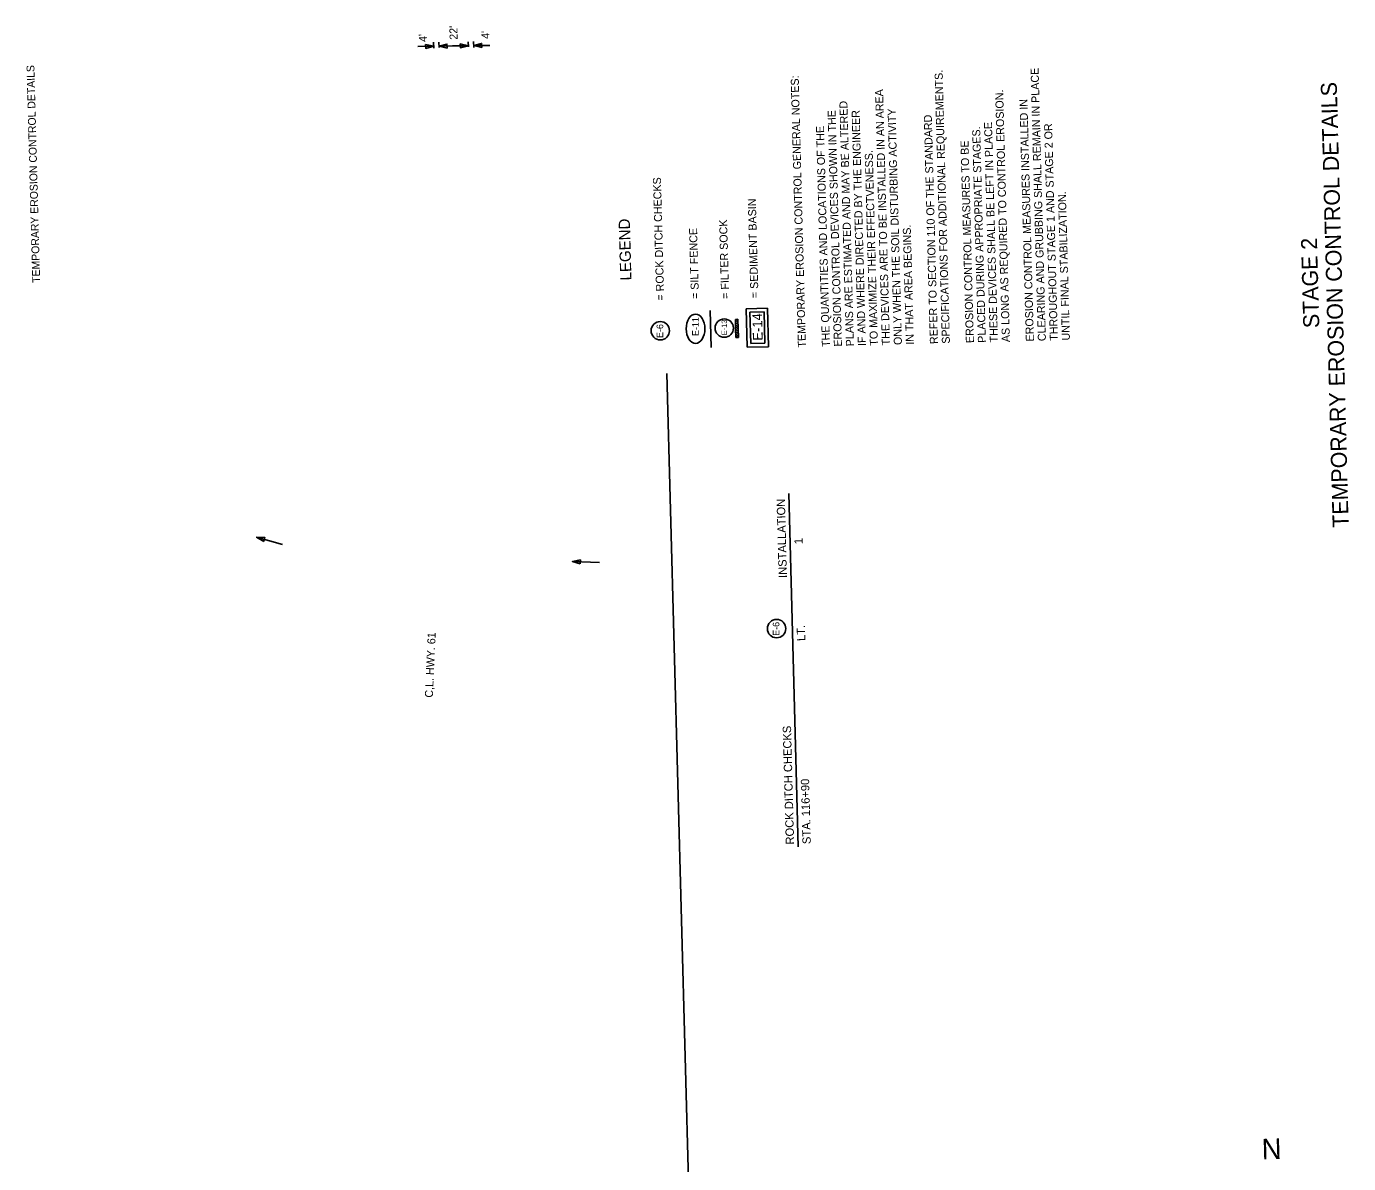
# Model space of a CAD drawing. Extents: x 1930579 to 1931599, y 596452 to 598574.
# Drawn here: x 1930608 to 1931599, y 597722 to 598574 of the extents above; entities that cross this region are included whole.
import ezdxf

# ---------------------------------------------------------------- set-up
doc = ezdxf.new("R2010")
doc.units = 0
for name, color, linetype in [('Default', 7, 'Continuous'), ('R_Annotation', 7, 'Continuous'), ('R_Border', 7, 'Continuous'), ('R_Erosion', 7, 'Continuous')]:
    doc.layers.add(name, color=color, linetype=linetype)

msp = doc.modelspace()

# ---------------------------------------------------------------- linework, layer by layer
at = {"layer": 'Default'}
msp.add_line((1931186.46, 597959.13), (1931179.35, 598224.08), dxfattribs=at)
at = {"layer": 'R_Annotation'}
for p, q in [((1930913.15, 598559.55), (1930901.15, 598559.36)), ((1930913.17, 598558.16), (1930913.1, 598562.55)), ((1930917.17, 598558.69), (1930917.1, 598562.61)), ((1930917.15, 598559.61), (1930939.15, 598559.96)), ((1930929.15, 598559.8), (1930917.15, 598559.61)), ((1930939.15, 598559.96), (1930927.15, 598559.77)), ((1930939.16, 598559.05), (1930939.1, 598562.96)), ((1930943.17, 598558.62), (1930943.1, 598563.03)), ((1930955.15, 598560.22), (1930943.15, 598560.03)), ((1930780.38, 598191.25), (1930799.88, 598185.77)), ((1931017.13, 598173), (1931037.38, 598172.23))]:
    msp.add_line(p, q, dxfattribs=at)
for points in [[(1930907.13, 598560.95), (1930913.15, 598559.55), (1930907.18, 598557.95)], [(1930923.17, 598558.21), (1930917.15, 598559.61), (1930923.13, 598561.21)], [(1930923.17, 598558.21), (1930917.15, 598559.61), (1930923.13, 598561.21)], [(1930933.13, 598561.37), (1930939.15, 598559.96), (1930933.17, 598558.37)], [(1930933.13, 598561.37), (1930939.15, 598559.96), (1930933.17, 598558.37)], [(1930949.17, 598558.62), (1930943.15, 598560.03), (1930949.12, 598561.62)], [(1930785.75, 598188.18), (1930780.38, 598191.25), (1930786.56, 598191.07)], [(1931023.07, 598171.27), (1931017.13, 598173), (1931023.19, 598174.27)]]:
    msp.add_lwpolyline(points, close=True, dxfattribs=at)
at = {"layer": 'R_Border'}
msp.add_line((1931105.18, 597672.96), (1931087.97, 598314.03), dxfattribs=at)
at = {"layer": 'R_Erosion'}
for p, q in [((1931147.54, 598362.6), (1931163.53, 598363.03)), ((1931148.31, 598333.76), (1931147.54, 598362.6)), ((1931150.32, 598359.97), (1931160.9, 598360.26)), ((1931150.94, 598336.54), (1931150.32, 598359.97)), ((1931161.53, 598336.83), (1931160.9, 598360.26)), ((1931164.31, 598334.2), (1931163.53, 598363.03)), ((1931139.39, 598354.7), (1931141.26, 598354.75)), ((1931141.32, 598352.47), (1931139.4, 598354.3)), ((1931141.37, 598350.71), (1931139.45, 598352.53)), ((1931141.42, 598348.94), (1931139.49, 598350.76)), ((1931141.46, 598347.42), (1931139.53, 598349.25)), ((1931141.51, 598345.66), (1931139.58, 598347.48)), ((1931141.28, 598354.24), (1931140.75, 598354.74)), ((1931141.55, 598343.89), (1931139.63, 598345.71)), ((1931141.6, 598342.12), (1931139.68, 598343.95)), ((1931140.86, 598341.1), (1931139.72, 598342.18)), ((1931139.75, 598341.07), (1931141.63, 598341.12)), ((1931148.31, 598333.76), (1931164.31, 598334.2)), ((1931150.94, 598336.54), (1931161.53, 598336.83))]:
    msp.add_line(p, q, dxfattribs=at)
for points in [[(1931121.24, 598333.54), (1931120.48, 598361.33)], [(1931139.39, 598354.7), (1931139.57, 598347.89)], [(1931139.57, 598347.89), (1931139.75, 598341.07)], [(1931141.26, 598354.75), (1931141.44, 598347.94)], [(1931141.44, 598347.94), (1931141.63, 598341.12)]]:
    msp.add_lwpolyline(points, dxfattribs=at)
for centre in [(1931083.1, 598346.16), (1931131.03, 598348.11), (1931170.26, 598122.76)]:
    msp.add_circle(centre, 6.88, dxfattribs=at)
msp.add_ellipse((1931109.52, 598347.64), major_axis=(0, 10.96), ratio=0.638788, dxfattribs=at)

# ---------------------------------------------------------------- texts
at = {"layer": 'Default'}
for s, p in [('INSTALLATION', (1931178.11, 598160.81)), ('1', (1931189.93, 598186.14)), (' LT.', (1931191.95, 598111.17)), ('ROCK DITCH CHECKS', (1931183.47, 597960.89)), ('STA. 116+90', (1931195.97, 597961.22))]:
    msp.add_text(s, height=6.25, rotation=91.53769, dxfattribs=at).set_placement(p)
at = {"layer": 'R_Annotation'}
for s, height, rotation, p in [("4'", 6, 91.53769, (1930908.14, 598562.83)), ("22'", 6, 91.53769, (1930931.14, 598564.51)), ("4'", 6, 91.53769, (1930955.04, 598565.15)), ('TEMPORARY EROSION CONTROL DETAILS', 12, 91.53769, (1931599.31, 598198.59)), ('STAGE 2', 12, 91.53769, (1931577.29, 598348.27)), ('C,L. HWY. 61', 6, 87.4295, (1930912.49, 598070.87))]:
    msp.add_text(s, height=height, rotation=rotation, dxfattribs=at).set_placement(p)
at = {"layer": 'R_Border'}
for s, height, rotation, p in [('TEMPORARY EROSION CONTROL DETAILS', 5.862, 91.53769, (1930618.06, 598382.18)), ('TEMPORARY EROSION CONTROL GENERAL NOTES:', 6, 91.53769, (1931192.31, 598333.6)), ('SPECIFICATIONS FOR ADDITIONAL REQUIREMENTS.', 6, 91.53769, (1931300.27, 598336.5)), ('CLEARING AND GRUBBING SHALL REMAIN IN PLACE ', 6, 91.53769, (1931372.24, 598338.43)), ('THE DEVICES ARE TO BE INSTALLED IN AN AREA ', 6, 91.53769, (1931255.28, 598335.29)), ('AS LONG AS REQUIRED TO CONTROL EROSION.', 6, 91.53769, (1931345.25, 598337.7)), ('PLANS ARE ESTIMATED AND MAY BE ALTERED ', 6, 91.53769, (1931228.29, 598334.56)), ('EROSION CONTROL MEASURES INSTALLED IN', 6, 91.53769, (1931363.24, 598338.19)), ('EROSION CONTROL DEVICES SHOWN IN THE ', 6, 91.53769, (1931219.3, 598334.32)), ('IF AND WHERE DIRECTED BY THE ENGINEER ', 6, 91.53769, (1931237.29, 598334.81)), ('ONLY WHEN THE SOIL DISTURBING ACTIVITY', 6, 91.53769, (1931264.28, 598335.53)), ('REFER TO SECTION 110 OF THE STANDARD ', 6, 91.53769, (1931291.27, 598336.26)), ('THE QUANTITIES AND LOCATIONS OF THE', 6, 91.53769, (1931210.3, 598334.08)), ('PLACED DURING APPROPRIATE STAGES. ', 6, 91.53769, (1931327.26, 598337.22)), ('THESE DEVICES SHALL BE LEFT IN PLACE ', 6, 91.53769, (1931336.25, 598337.46)), ('THROUGHOUT STAGE 1 AND STAGE 2 OR ', 6, 91.53769, (1931381.24, 598338.67)), ('EROSION CONTROL MEASURES TO BE', 6, 91.53769, (1931318.26, 598336.98)), ('TO MAXIMIZE THEIR EFFECTVENESS. ', 6, 91.53769, (1931246.29, 598335.05)), ('UNTIL FINAL STABILIZATION.', 6, 91.53769, (1931390.24, 598338.91)), ('IN THAT AREA BEGINS.', 6, 91.53769, (1931273.28, 598335.77)), ('N', 15.38, 1.53769, (1931534.27, 597724.62))]:
    msp.add_text(s, height=height, rotation=rotation, dxfattribs=at).set_placement(p)
at = {"layer": 'R_Erosion'}
for s, height, rotation, p in [('= ROCK DITCH CHECKS', 6, 91.53769, (1931086.04, 598368.84)), ('= SEDIMENT BASIN', 6, 91.53769, (1931156.7, 598370.74)), ('LEGEND', 8.439, 91.53769, (1931061.49, 598383.96)), ('= FILTER SOCK', 6, 91.53769, (1931134.75, 598370.15)), ('= SILT FENCE', 6, 91.53769, (1931112.07, 598370.06)), ('E-14', 7.303, 91.53628, (1931159.9, 598338.8)), ('E-6 ', 4.999, 90, (1931085.27, 598340.74)), ('E-11', 4.999, 90, (1931111.98, 598342.22)), ('E-13', 4, 90, (1931133.03, 598342.83)), ('E-6 ', 5, 90, (1931172.43, 598117.34))]:
    msp.add_text(s, height=height, rotation=rotation, dxfattribs=at).set_placement(p)

doc.saveas('drawing.dxf')
